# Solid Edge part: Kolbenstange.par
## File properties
Username: bmolnar
Dokumentum tartalom típus: 0
Author: bmolnar
Last saved by: bmolnar
Revision: 85
Sűrűség: 0,000 kg/m^3
Pontosság: 0,990
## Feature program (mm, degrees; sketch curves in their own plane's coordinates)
base feature "unnamed BaseFeature 1"
sketch for "unnamed Protrusion 1" plane through (0, 0, 0) normal (-1, 0, 0) x-axis (0, -1, 0)
  circle centre (0, 0) radius 40
extrude "unnamed Protrusion 1" add finite 19.15 along +normal
sketch for "Kihúzás_2" #1 plane through (0, 0, 0) normal (-1, 0, 0) x-axis (0, -1, 0)
  circle centre (0, 0) radius 10
sketch for "Kihúzás_2" #2 plane through (0, 0, 0) normal (-1, 0, 0) x-axis (0, -1, 0)
  circle centre (0, 0) radius 40
extrude "Kihúzás_2" add finite 10.8 along -normal
sketch for "Furat_1" plane through (133.5, 0, 0) normal (1, 0, 0) x-axis (0, 1, 0)
  hole centre (0, 0) bore radius 4.188
hole "Furat_1" nominal diameter 10 finite  VBottomAngle = 118 deg; ThreadDepth = 13.5 mm
chamfer "Letörés_1" setback 0.8  SetBackValue2 = 45 deg
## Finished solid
Body 1: solid body, 17 faces, 23 edges, 8 vertices.
  Faces by surface: plane 7, cylinder 5, cone 3, torus 2
  Edges by curve: circle 13, line 6, curve on surface 2, ellipse 2
Bounding box of the edges (mm; curved faces can reach further): 156.150 x 80.000 x 80.000, from (-19.15, -40, -40) to (137, 40, 40).
Cylindrical faces by radius (mm): R4.188 x2, R5.125 x1, R10 x1, R40 x1
Conical faces (half-angle, radius in mm at the cone's reference point): 45 deg R4.988 x1, 45 deg R5.225 x1, 59 deg R4.188 x1
Toroidal faces (ring radius, tube radius in mm): R4.925 r0.2 x1, R8.2 r1.8 x1
Planar faces by outward normal: +x 2, +z 1, -x 1, -z 1, oblique 2
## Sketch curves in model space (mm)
circle centre (0, 0, 0) radius 40
circle centre (0, 0, 0) radius 10
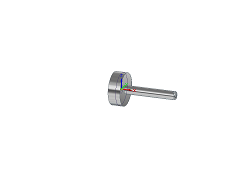
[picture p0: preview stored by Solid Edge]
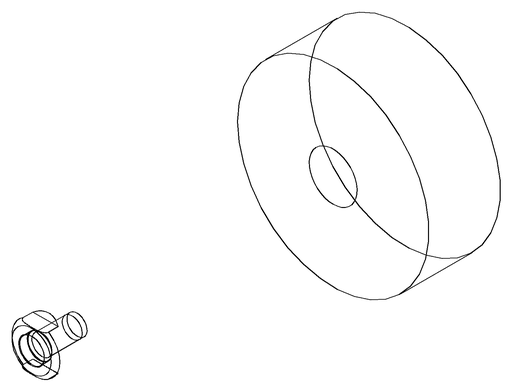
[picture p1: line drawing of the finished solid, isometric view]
